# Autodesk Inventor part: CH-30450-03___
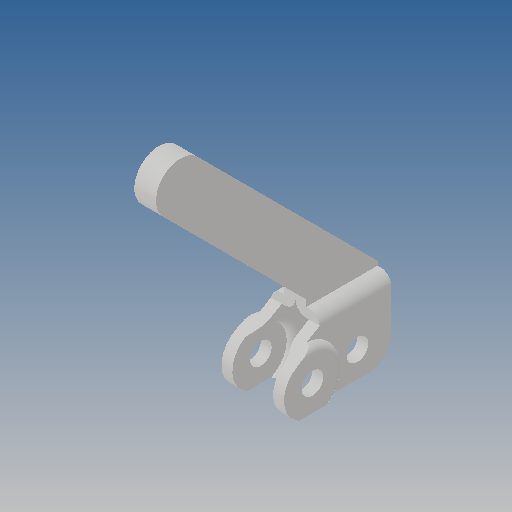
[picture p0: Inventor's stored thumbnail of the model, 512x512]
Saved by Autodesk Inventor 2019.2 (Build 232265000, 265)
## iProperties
Created: 2010-06
Part Number: CH-30450-03___
Material: Ogólny
Document SubType Name: Modeling
Designer: CADENGINEERING4
Density: 1 g/cm^3
Appearance: Domyślna
Author: CADENGINEERING4
Revision Number: ANY
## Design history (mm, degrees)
feature "NONE"
node "Bryła1"
